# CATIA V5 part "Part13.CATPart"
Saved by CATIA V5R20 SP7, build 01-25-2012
Part number: squelette corps vérin droit
Bounding box of the stored display mesh (mm): x -17.69 to -7.071, y -54 to -25.951, z -7.6 to -6.916
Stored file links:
  F:\Travaux\Modélisations\CFAO_2011\CFAO_2011_MMS\CFAO_2011_MMS_DONE\CFAO_2011_MMS_jboiteux\Catia\Part13.CATPart
  U:\finthinkmotion\stepper.CATProduct
  F:\Travaux\Modélisations\CFAO_2011\CFAO_2011_MMS\CFAO_2011_MMS_DONE\CFAO_2011_MMS_jboiteux\Catia\Part1.CATPart
  F:\Travaux\Modélisations\CFAO_2011\CFAO_2011_MMS\CFAO_2011_MMS_DONE\CFAO_2011_MMS_jboiteux\Catia\part3.CATPart
  F:\Travaux\Modélisations\CFAO_2011\CFAO_2011_MMS\CFAO_2011_MMS_DONE\CFAO_2011_MMS_jboiteux\Catia\Part14.CATPart
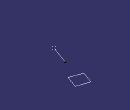
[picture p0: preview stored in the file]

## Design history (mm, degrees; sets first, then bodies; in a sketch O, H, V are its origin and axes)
Set1
  Point1: linked copy from another document
  Line1 to Line3: linked copy from another document
Body1 (main body)
  Point2: type OnCurve, Support Line3, Ratio 1
  Line4: type PtDir, RefPoint Point2, Direction Line1, Start 0, End 30
  Plane1: type 2Lines, Element1 Line1, Element2 Line2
